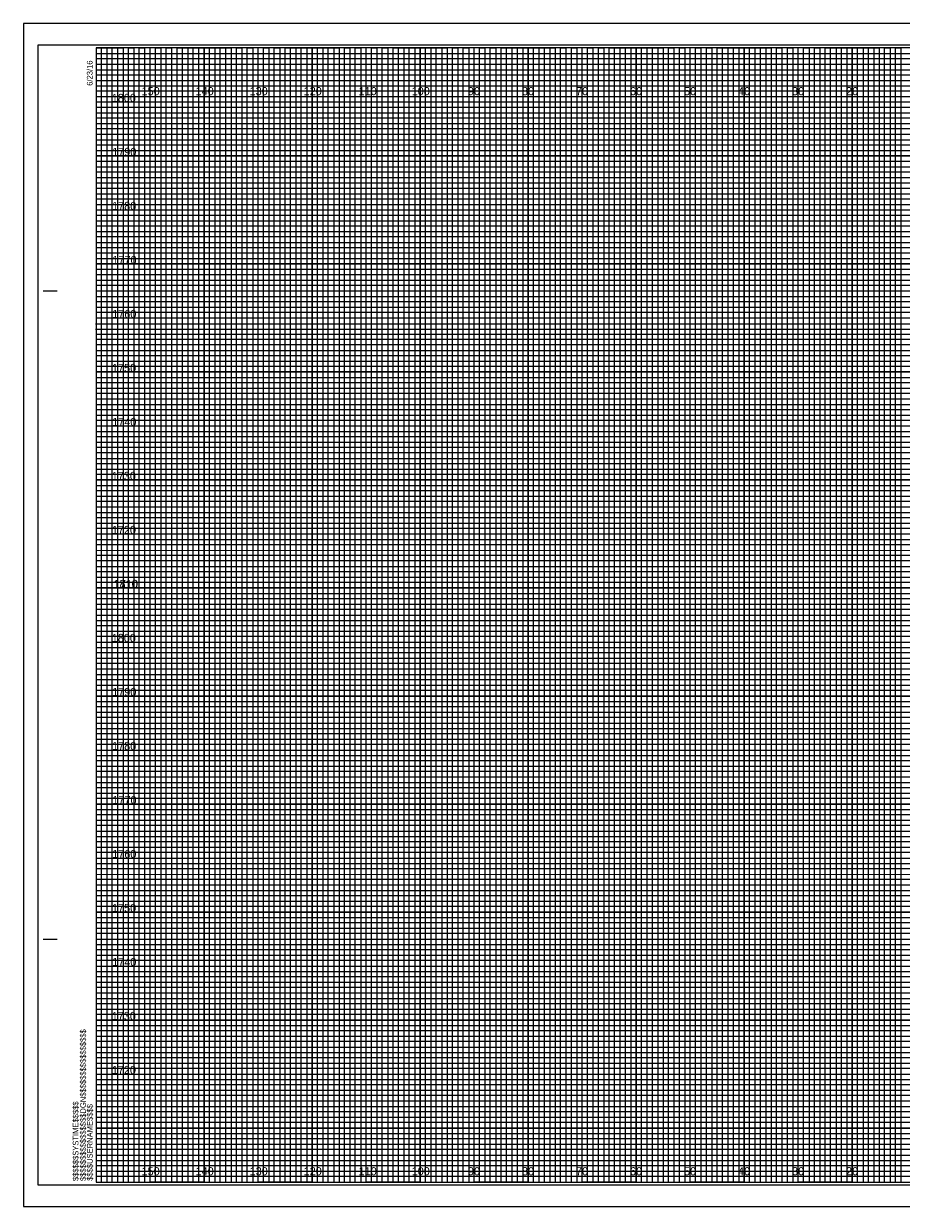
# Model space of a CAD drawing. Extents: x -15 to 323, y -5 to 6170.
# Drawn here: x -13.4 to 149.1, y 4835.5 to 5054.5 of the extents above; entities that cross this region are included whole.
import ezdxf

# ---------------------------------------------------------------- set-up
doc = ezdxf.new("R2010")
doc.units = 0
for name, color, linetype in [('Prop XS DDE', 7, 'Continuous'), ('Prop XS DDE Slope Text', 7, 'Continuous'), ('Prop XS DDE Text', 7, 'Continuous'), ('Prop XS Earthwork Shape', 7, 'Continuous'), ('Prop XS Noise Wall', 7, 'Continuous'), ('Prop XS Retaining Wall', 7, 'Continuous'), ('Prop XS Station Labels', 7, 'Continuous'), ('Scratch_Level_3', 7, 'Continuous'), ('Scratch_Level_7', 7, 'Continuous'), ('Scratch_Level_8', 7, 'Continuous'), ('Sheet Cross Section Grid Minor 1 CELL', 7, 'Continuous')]:
    doc.layers.add(name, color=color, linetype=linetype)

msp = doc.modelspace()

# ---------------------------------------------------------------- linework, layer by layer
at = {"layer": 'Prop XS DDE'}
msp.add_lwpolyline([(-13.4, 4835.5), (323.3, 4835.5), (323.3, 5054.5), (-13.4, 5054.5)], close=True, dxfattribs=at)
at = {"layer": 'Prop XS DDE Slope Text'}
msp.add_lwpolyline([(-10.8, 4839.5), (322.4, 4839.5), (322.4, 5050.5), (-10.8, 5050.5)], close=True, dxfattribs=at)
at = {"layer": 'Prop XS DDE Text'}
for p, q in [((10, 4840), (10, 5050)), ((20, 4840), (20, 5050)), ((30, 4840), (30, 5050)), ((40, 4840), (40, 5050)), ((50, 4840), (50, 5050)), ((60, 4840), (60, 5050)), ((70, 4840), (70, 5050)), ((80, 4840), (80, 5050)), ((90, 4840), (90, 5050)), ((100, 4840), (100, 5050)), ((110, 4840), (110, 5050)), ((120, 4840), (120, 5050)), ((130, 4840), (130, 5050)), ((140, 4840), (140, 5050)), ((0, 5040), (320, 5040)), ((0, 5030), (320, 5030)), ((0, 5020), (320, 5020)), ((0, 5010), (320, 5010)), ((0, 5000), (320, 5000)), ((0, 4990), (320, 4990)), ((0, 4980), (320, 4980)), ((0, 4970), (320, 4970)), ((0, 4960), (320, 4960)), ((0, 4950), (320, 4950)), ((0, 4940), (320, 4940)), ((0, 4930), (320, 4930)), ((0, 4920), (320, 4920)), ((0, 4910), (320, 4910)), ((0, 4900), (320, 4900)), ((0, 4890), (320, 4890)), ((0, 4880), (320, 4880)), ((0, 4870), (320, 4870)), ((0, 4860), (320, 4860)), ((0, 4850), (320, 4850))]:
    msp.add_line(p, q, dxfattribs=at)
at = {"layer": 'Prop XS Earthwork Shape'}
for p, q in [((10, 5050), (0, 5050)), ((10, 4840), (10, 5050)), ((30, 5050), (20, 5050)), ((20, 5050), (20, 4840)), ((30, 4840), (30, 5050)), ((50, 5050), (40, 5050)), ((40, 5050), (40, 4840)), ((50, 4840), (50, 5050)), ((70, 5050), (60, 5050)), ((60, 5050), (60, 4840)), ((70, 4840), (70, 5050)), ((90, 5050), (80, 5050)), ((80, 5050), (80, 4840)), ((90, 4840), (90, 5050)), ((110, 5050), (100, 5050)), ((100, 5050), (100, 4840)), ((110, 4840), (110, 5050)), ((130, 5050), (120, 5050)), ((120, 5050), (120, 4840)), ((130, 4840), (130, 5050)), ((150, 5050), (140, 5050)), ((140, 5050), (140, 4840)), ((20, 4840), (10, 4840)), ((40, 4840), (30, 4840)), ((60, 4840), (50, 4840)), ((80, 4840), (70, 4840)), ((100, 4840), (90, 4840)), ((120, 4840), (110, 4840)), ((140, 4840), (130, 4840))]:
    msp.add_line(p, q, dxfattribs=at)
for points in [[(0, 5040), (320, 5040), (320, 5030), (0, 5030)], [(0, 5020), (320, 5020), (320, 5010), (0, 5010)], [(0, 5000), (320, 5000), (320, 4990), (0, 4990)], [(0, 4980), (320, 4980), (320, 4970), (0, 4970)], [(0, 4960), (320, 4960), (320, 4950), (0, 4950)], [(0, 4940), (320, 4940), (320, 4930), (0, 4930)], [(0, 4920), (320, 4920), (320, 4910), (0, 4910)], [(0, 4900), (320, 4900), (320, 4890), (0, 4890)], [(0, 4880), (320, 4880), (320, 4870), (0, 4870)], [(0, 4860), (320, 4860), (320, 4850), (0, 4850)]]:
    msp.add_lwpolyline(points, dxfattribs=at)
at = {"layer": 'Prop XS Noise Wall'}
for p, q in [((-9.8, 5005), (-7.3, 5005)), ((-9.7, 5005), (-7.2, 5005)), ((-9.8, 4885), (-7.3, 4885)), ((-9.7, 4885), (-7.2, 4885)), ((0, 4840), (0, 4840)), ((0, 4840), (0, 4840)), ((0, 4840), (0, 4840)), ((0, 4840), (0, 4840)), ((0, 4840), (0, 4840)), ((0, 4840), (0, 4840)), ((0, 4840), (0, 4840))]:
    msp.add_line(p, q, dxfattribs=at)
msp.add_lwpolyline([(320, 5050), (0, 5050), (0, 4840), (320, 4840)], close=True, dxfattribs=at)
at = {"layer": 'Prop XS Retaining Wall'}
for points in [[(0, 4840), (1, 4840), (1, 5050), (2, 5050), (2, 4840)], [(2, 4840), (3, 4840), (3, 5050), (4, 5050), (4, 4840)], [(5, 4840), (6, 4840), (6, 5050), (7, 5050), (7, 4840)], [(7, 4840), (8, 4840), (8, 5050), (9, 5050), (9, 4840)], [(10, 4840), (11, 4840), (11, 5050), (12, 5050), (12, 4840)], [(12, 4840), (13, 4840), (13, 5050), (14, 5050), (14, 4840)], [(15, 4840), (16, 4840), (16, 5050), (17, 5050), (17, 4840)], [(17, 4840), (18, 4840), (18, 5050), (19, 5050), (19, 4840)], [(20, 4840), (21, 4840), (21, 5050), (22, 5050), (22, 4840)], [(22, 4840), (23, 4840), (23, 5050), (24, 5050), (24, 4840)], [(25, 4840), (26, 4840), (26, 5050), (27, 5050), (27, 4840)], [(27, 4840), (28, 4840), (28, 5050), (29, 5050), (29, 4840)], [(30, 4840), (31, 4840), (31, 5050), (32, 5050), (32, 4840)], [(32, 4840), (33, 4840), (33, 5050), (34, 5050), (34, 4840)], [(35, 4840), (36, 4840), (36, 5050), (37, 5050), (37, 4840)], [(37, 4840), (38, 4840), (38, 5050), (39, 5050), (39, 4840)], [(40, 4840), (41, 4840), (41, 5050), (42, 5050), (42, 4840)], [(42, 4840), (43, 4840), (43, 5050), (44, 5050), (44, 4840)], [(45, 4840), (46, 4840), (46, 5050), (47, 5050), (47, 4840)], [(47, 4840), (48, 4840), (48, 5050), (49, 5050), (49, 4840)], [(50, 4840), (51, 4840), (51, 5050), (52, 5050), (52, 4840)], [(52, 4840), (53, 4840), (53, 5050), (54, 5050), (54, 4840)], [(55, 4840), (56, 4840), (56, 5050), (57, 5050), (57, 4840)], [(57, 4840), (58, 4840), (58, 5050), (59, 5050), (59, 4840)], [(60, 4840), (61, 4840), (61, 5050), (62, 5050), (62, 4840)], [(62, 4840), (63, 4840), (63, 5050), (64, 5050), (64, 4840)], [(65, 4840), (66, 4840), (66, 5050), (67, 5050), (67, 4840)], [(67, 4840), (68, 4840), (68, 5050), (69, 5050), (69, 4840)], [(70, 4840), (71, 4840), (71, 5050), (72, 5050), (72, 4840)], [(72, 4840), (73, 4840), (73, 5050), (74, 5050), (74, 4840)], [(75, 4840), (76, 4840), (76, 5050), (77, 5050), (77, 4840)], [(77, 4840), (78, 4840), (78, 5050), (79, 5050), (79, 4840)], [(80, 4840), (81, 4840), (81, 5050), (82, 5050), (82, 4840)], [(82, 4840), (83, 4840), (83, 5050), (84, 5050), (84, 4840)], [(85, 4840), (86, 4840), (86, 5050), (87, 5050), (87, 4840)], [(87, 4840), (88, 4840), (88, 5050), (89, 5050), (89, 4840)], [(90, 4840), (91, 4840), (91, 5050), (92, 5050), (92, 4840)], [(92, 4840), (93, 4840), (93, 5050), (94, 5050), (94, 4840)], [(95, 4840), (96, 4840), (96, 5050), (97, 5050), (97, 4840)], [(97, 4840), (98, 4840), (98, 5050), (99, 5050), (99, 4840)], [(100, 4840), (101, 4840), (101, 5050), (102, 5050), (102, 4840)], [(102, 4840), (103, 4840), (103, 5050), (104, 5050), (104, 4840)], [(105, 4840), (106, 4840), (106, 5050), (107, 5050), (107, 4840)], [(107, 4840), (108, 4840), (108, 5050), (109, 5050), (109, 4840)], [(110, 4840), (111, 4840), (111, 5050), (112, 5050), (112, 4840)], [(112, 4840), (113, 4840), (113, 5050), (114, 5050), (114, 4840)], [(115, 4840), (116, 4840), (116, 5050), (117, 5050), (117, 4840)], [(117, 4840), (118, 4840), (118, 5050), (119, 5050), (119, 4840)], [(120, 4840), (121, 4840), (121, 5050), (122, 5050), (122, 4840)], [(122, 4840), (123, 4840), (123, 5050), (124, 5050), (124, 4840)], [(125, 4840), (126, 4840), (126, 5050), (127, 5050), (127, 4840)], [(127, 4840), (128, 4840), (128, 5050), (129, 5050), (129, 4840)], [(130, 4840), (131, 4840), (131, 5050), (132, 5050), (132, 4840)], [(132, 4840), (133, 4840), (133, 5050), (134, 5050), (134, 4840)], [(135, 4840), (136, 4840), (136, 5050), (137, 5050), (137, 4840)], [(137, 4840), (138, 4840), (138, 5050), (139, 5050), (139, 4840)], [(140, 4840), (141, 4840), (141, 5050), (142, 5050), (142, 4840)], [(142, 4840), (143, 4840), (143, 5050), (144, 5050), (144, 4840)], [(145, 4840), (146, 4840), (146, 5050), (147, 5050), (147, 4840)], [(147, 4840), (148, 4840), (148, 5050), (149, 5050), (149, 4840)]]:
    msp.add_lwpolyline(points, dxfattribs=at)
at = {"layer": 'Prop XS Station Labels'}
for points in [[(0, 5050), (5, 5050), (5, 4840), (15, 4840), (15, 5050), (25, 5050), (25, 4840), (35, 4840), (35, 5050), (45, 5050), (45, 4840), (55, 4840), (55, 5050), (65, 5050), (65, 4840), (75, 4840), (75, 5050), (85, 5050), (85, 4840), (95, 4840), (95, 5050), (105, 5050), (105, 4840), (115, 4840), (115, 5050), (125, 5050), (125, 4840), (135, 4840), (135, 5050), (145, 5050), (145, 4840), (155, 4840)], [(0, 5045), (275, 5045)], [(0, 5025), (320, 5025), (320, 5035), (0, 5035)], [(0, 5005), (320, 5005), (320, 5015), (0, 5015)], [(0, 4985), (320, 4985), (320, 4995), (0, 4995)], [(0, 4965), (320, 4965), (320, 4975), (0, 4975)], [(0, 4945), (320, 4945), (320, 4955), (0, 4955)], [(0, 4925), (320, 4925), (320, 4935), (0, 4935)], [(0, 4905), (320, 4905), (320, 4915), (0, 4915)], [(0, 4885), (320, 4885), (320, 4895), (0, 4895)], [(0, 4865), (320, 4865), (320, 4875), (0, 4875)], [(0, 4845), (320, 4845), (320, 4855), (0, 4855)]]:
    msp.add_lwpolyline(points, dxfattribs=at)
at = {"layer": 'Scratch_Level_7'}
for p, q in [((323.3, 5054.5), (-13.4, 5054.5)), ((-13.4, 5054.5), (-13.4, 4835.5)), ((-13.4, 4835.5), (323.3, 4835.5))]:
    msp.add_line(p, q, dxfattribs=at)
at = {"layer": 'Sheet Cross Section Grid Minor 1 CELL'}
for p, q in [((0, 5049), (260, 5049)), ((260, 5047.98), (0, 5047.98)), ((0, 5047.98), (0, 5047)), ((0, 5047), (260, 5047)), ((260, 5045.89), (0, 5045.89)), ((0, 5045.89), (0, 5044)), ((0, 5044), (320, 5044))]:
    msp.add_line(p, q, dxfattribs=at)
for points in [[(0, 5043), (270, 5043), (320, 5043), (320, 5042), (0, 5042)], [(0, 5041), (320, 5041), (320, 5039), (0, 5039)], [(0, 5038), (320, 5038), (320, 5037), (0, 5036.98)], [(0, 5036), (320, 5036), (320, 5034), (0, 5034)], [(0, 5033), (320, 5033), (320, 5032), (0, 5032)], [(0, 5031), (320, 5031), (320, 5029), (0, 5029)], [(0, 5028), (320, 5028), (320, 5027), (0, 5027)], [(0, 5026), (320, 5026), (320, 5024), (0, 5024)], [(0, 5023), (320, 5023), (320, 5022), (0, 5022)], [(0, 5021), (320, 5021), (320, 5019), (0, 5019)], [(0, 5018), (320, 5018), (320, 5017), (0, 5017)], [(0, 5016), (320, 5016), (320, 5013.95), (320, 5013), (320, 5012), (0, 5012)], [(0, 5014), (320, 5014), (320, 5013), (0, 5013)], [(0, 5011), (320, 5011), (320, 5009), (0, 5009.03)], [(0, 5009.03), (320, 5009), (320, 5008), (0, 5008)], [(0, 5007), (320, 5007), (320, 5006), (0, 5006)], [(0, 5004), (320, 5004), (320, 5003), (0, 5003)], [(0, 5002), (320, 5002), (320, 5001), (0, 5001)], [(-0.07, 4998.89), (320, 4998.89), (320, 4997.88), (-0.07, 4997.88)], [(0, 4997), (320, 4997), (320, 4996), (0, 4996)], [(0, 4994), (320, 4994), (320, 4993), (0, 4993)], [(0, 4992), (320, 4992), (320, 4991), (0, 4991)], [(0, 4989), (320, 4989), (320, 4988), (0, 4988)], [(0, 4987), (320, 4987), (320, 4986), (0, 4986)], [(0, 4984), (320, 4984), (320, 4983), (0, 4983)], [(0, 4982), (320, 4982), (320, 4981), (0, 4981)], [(0, 4979), (320, 4979), (319.99, 4977.98), (0, 4978)], [(0, 4977), (320, 4977), (320, 4976), (0, 4976)], [(0, 4974), (320, 4974), (320, 4973), (0, 4973)], [(0, 4972), (320, 4972), (320, 4971), (0, 4971)], [(0, 4969), (320, 4969), (320, 4968), (0, 4968)], [(0, 4967), (320, 4967), (320, 4966), (0, 4966)], [(0, 4964), (320, 4964), (320, 4963), (0, 4963)], [(0, 4962), (320, 4962), (320, 4961), (0, 4961)], [(0, 4959), (320, 4959), (320, 4958), (0, 4958)], [(0, 4956.99), (320.07, 4956.91), (320, 4956), (0, 4956)], [(0, 4954), (320, 4954), (320, 4953), (0, 4953)], [(0, 4952), (320, 4952), (320, 4951), (0, 4951)], [(0, 4949), (320, 4949), (320, 4948), (0, 4948)], [(0, 4947), (320, 4947), (320, 4946), (0, 4946)], [(0, 4944), (320, 4944), (320, 4943), (0, 4943)], [(0, 4942), (320, 4942), (320, 4941), (0, 4941)], [(0, 4939), (320, 4939), (320, 4938), (0, 4938)], [(0, 4937), (320, 4937), (320, 4936), (0, 4936)], [(0, 4934), (320, 4934), (320, 4933), (0, 4933)], [(0, 4932), (320, 4932), (320, 4931), (0, 4931)], [(0, 4929), (320, 4929), (320, 4928), (0, 4928)], [(0, 4927), (320, 4927), (320, 4926), (0, 4926)], [(0, 4924), (320, 4924), (320, 4923), (0, 4923)], [(0, 4922), (320, 4922), (320, 4921), (0, 4921)], [(0, 4919), (320, 4919), (319.99, 4917.98), (0, 4918)], [(0, 4917), (320, 4917), (320, 4916), (0, 4916)], [(0, 4914), (320, 4914), (320, 4913), (0, 4913)], [(0, 4912), (320, 4912), (320, 4911), (0, 4911)], [(0, 4909), (320, 4909), (320, 4908), (0, 4908)], [(0, 4907), (320, 4907), (320, 4906), (0, 4906)], [(0, 4904), (320, 4904), (320, 4903), (0, 4903)], [(0, 4902), (320, 4902), (320, 4901), (0, 4901)], [(0, 4899), (320, 4899), (320, 4898), (0, 4898)], [(0, 4896.99), (320.07, 4896.91), (320, 4896), (0, 4896)], [(0, 4894), (320, 4894), (320, 4893), (0, 4893)], [(0, 4892), (320, 4892), (320, 4891), (0, 4891)], [(0, 4889), (320, 4889), (320, 4888), (0, 4888)], [(0, 4887), (320, 4887), (320, 4886), (0, 4886)], [(0, 4884), (320, 4884), (320, 4883), (0, 4883)], [(0, 4882), (320, 4882), (320, 4881), (0, 4881)], [(0, 4879), (320, 4879), (320, 4878), (0, 4878)], [(0, 4877), (320, 4877), (320, 4876), (0, 4876)], [(0, 4874), (320, 4874), (320, 4873), (0, 4873)], [(0, 4872), (320, 4872), (320, 4871), (0, 4871)], [(0, 4869), (320, 4869), (320, 4868), (0, 4868)], [(0, 4867), (320, 4867), (320, 4866), (0, 4866)], [(0, 4864), (320, 4864), (320, 4863), (0, 4863)], [(0, 4862), (320, 4862), (320, 4861), (0, 4861)], [(0, 4859), (320, 4859), (320, 4858), (0, 4858)], [(0, 4857), (320, 4857), (320, 4856), (0, 4856)], [(0, 4854), (320, 4854), (320, 4853), (0, 4853)], [(0, 4852), (320, 4852), (320, 4851), (0, 4851)], [(0, 4849), (320, 4849), (320, 4848), (0, 4848)], [(0, 4847), (320, 4847), (320, 4846), (0, 4846)], [(0, 4844), (320, 4844), (320, 4843), (0, 4843)], [(0, 4842), (320, 4842), (320, 4841), (0, 4841)]]:
    msp.add_lwpolyline(points, dxfattribs=at)

# ---------------------------------------------------------------- texts
at = {"layer": 'Prop XS Noise Wall'}
for s, p in [('6/23/16', (-0.65, 5043)), ('$$$$$$$$$$$$$$$$DGN$$$$$$$$$$$$$$$$', (-1.88, 4840.18)), ('$$$$$$SYSTIME$$$$$', (-3.26, 4840.18)), ('$$$$USERNAME$$$$', (-0.62, 4840.23))]:
    msp.add_text(s, height=1.05, rotation=90, dxfattribs=at).set_placement(p)
at = {"layer": 'Scratch_Level_3'}
for s, p in [('1800', (2.92, 5040)), ('1790', (3, 5030)), ('1780', (2.98, 5020)), ('1770', (3.04, 5010)), ('1760', (3, 5000)), ('1750', (2.96, 4990)), ('1740', (3, 4980)), ('1730', (2.92, 4970)), ('1720', (2.93, 4960)), ('1810', (3.25, 4950)), ('1710', (3.31, 4950)), ('1800', (2.92, 4940)), ('1790', (3, 4930)), ('1780', (2.98, 4920)), ('1770', (3.04, 4910)), ('1760', (3, 4900)), ('1750', (2.96, 4890)), ('1740', (3, 4880)), ('1730', (2.92, 4870)), ('1720', (2.93, 4860))]:
    msp.add_text(s, height=1.5, dxfattribs=at).set_placement(p)
at = {"layer": 'Scratch_Level_8'}
for s, p in [('150', (8.44, 5041.25)), ('140', (18.44, 5041.25)), ('130', (28.44, 5041.25)), ('120', (38.44, 5041.25)), ('110', (48.62, 5041.25)), ('100', (58.44, 5041.25)), ('90', (68.86, 5041.25)), ('80', (78.86, 5041.25)), ('70', (88.86, 5041.25)), ('60', (98.86, 5041.25)), ('50', (108.86, 5041.25)), ('40', (118.86, 5041.25)), ('30', (128.86, 5041.25)), ('20', (138.86, 5041.25)), ('150', (8.44, 4841.25)), ('140', (18.44, 4841.25)), ('130', (28.44, 4841.25)), ('120', (38.44, 4841.25)), ('110', (48.62, 4841.25)), ('100', (58.44, 4841.25)), ('90', (68.86, 4841.25)), ('80', (78.86, 4841.25)), ('70', (88.86, 4841.25)), ('60', (98.86, 4841.25)), ('50', (108.86, 4841.25)), ('40', (118.86, 4841.25)), ('30', (128.86, 4841.25)), ('20', (138.86, 4841.25))]:
    msp.add_text(s, height=1.5, dxfattribs=at).set_placement(p)

doc.saveas('drawing.dxf')
